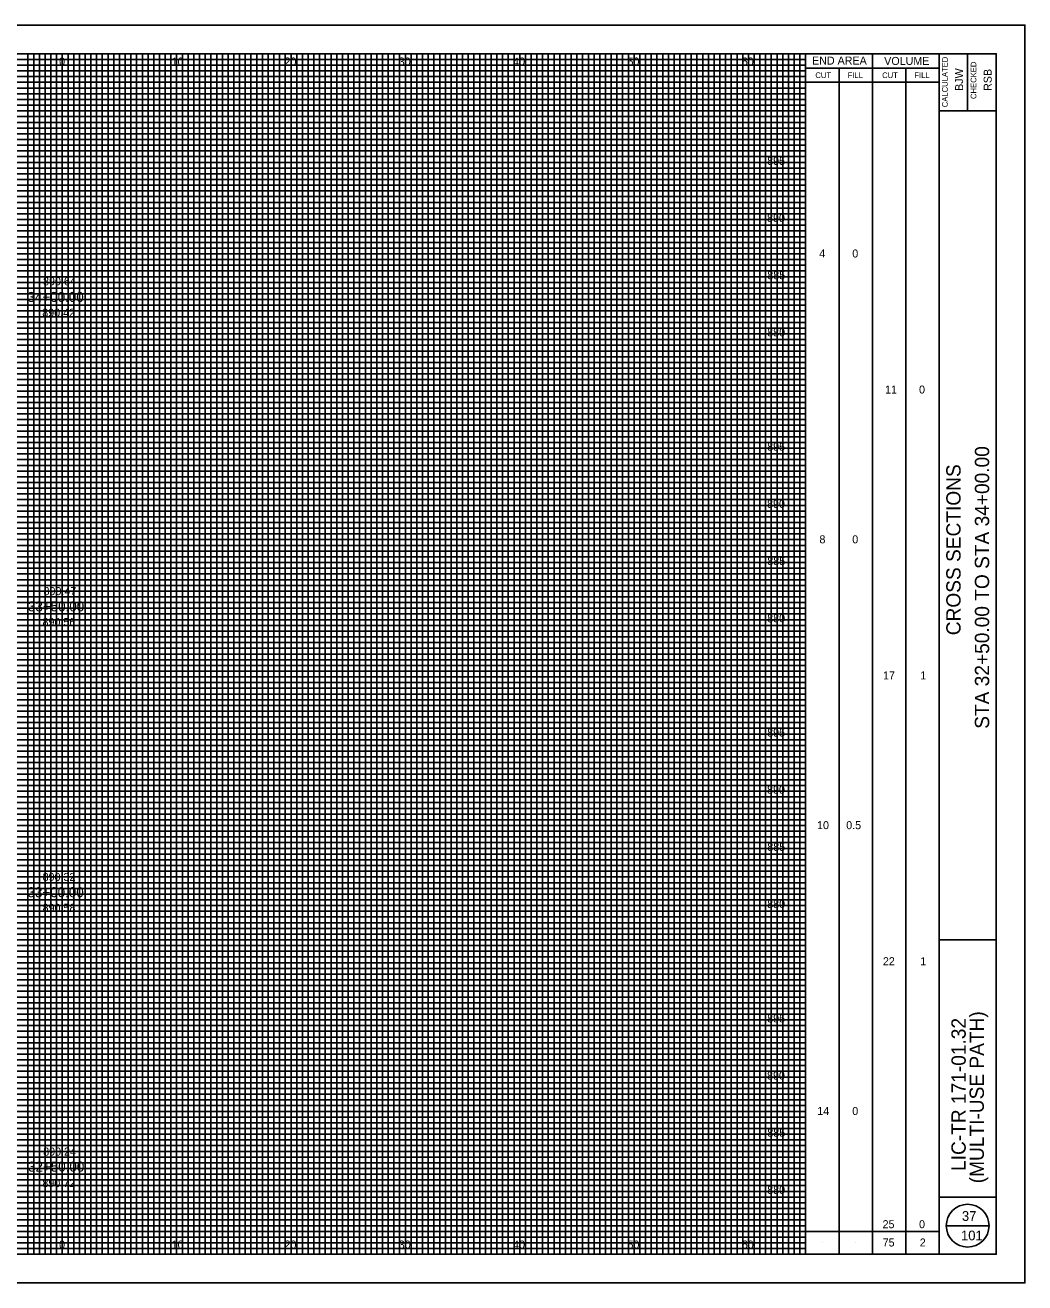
# Model space of a CAD drawing. Extents: x -10 to 160, y -2 to 2522.
# Drawn here: x 72.6 to 160, y 1032.5 to 1142.5 of the extents above; entities that cross this region are included whole.
import ezdxf

# ---------------------------------------------------------------- set-up
doc = ezdxf.new("R2010")
doc.units = 0
for name, color, linetype in [('GK_Cells', 7, 'Continuous'), ('GK_Patterns', 7, 'Continuous'), ('TX_P_10', 7, 'Continuous'), ('TX_X_10', 7, 'Continuous'), ('XS_P_Finished_Grade_Seeded', 7, 'Continuous'), ('XS_P_Pavt_Surface', 7, 'Continuous'), ('XS_P_Subgrade', 7, 'Continuous'), ('XS_X_Ground_Line', 7, 'Continuous')]:
    doc.layers.add(name, color=color, linetype=linetype)

msp = doc.modelspace()

# ---------------------------------------------------------------- linework, layer by layer
at = {"layer": 'GK_Cells'}
msp.add_lwpolyline([(-10, 1032.5), (160, 1032.5), (160, 1142.5), (-10, 1142.5)], close=True, dxfattribs=at)
at = {"layer": 'TX_P_10'}
for p, q in [((140.83, 1035), (140.83, 1140)), ((146.67, 1035), (146.67, 1140)), ((140.83, 1138.75), (152.5, 1138.75)), ((143.75, 1035), (143.75, 1138.75)), ((149.58, 1035), (149.58, 1138.75)), ((140.83, 1137.5), (152.5, 1137.5)), ((153.12, 1037.5), (156.88, 1037.5)), ((140.83, 1037), (152.5, 1037)), ((142.29, 1036), (142.29, 1036)), ((145.21, 1036), (145.21, 1036)), ((148.12, 1036), (148.12, 1036)), ((151.04, 1036), (151.04, 1036))]:
    msp.add_line(p, q, dxfattribs=at)
msp.add_circle((155, 1037.5), 1.87, dxfattribs=at)
at = {"layer": 'TX_X_10'}
for p, q in [((75.83, 1035), (75.83, 1140)), ((80.83, 1035), (80.83, 1140)), ((85.83, 1035), (85.83, 1140)), ((90.83, 1035), (90.83, 1140)), ((95.83, 1035), (95.83, 1140)), ((100.83, 1035), (100.83, 1140)), ((105.83, 1035), (105.83, 1140)), ((110.83, 1035), (110.83, 1140)), ((115.83, 1035), (115.83, 1140)), ((120.83, 1035), (120.83, 1140)), ((125.83, 1035), (125.83, 1140)), ((130.83, 1035), (130.83, 1140)), ((135.83, 1035), (135.83, 1140)), ((5.83, 1135), (140.83, 1135)), ((5.83, 1130), (140.83, 1130)), ((5.83, 1125), (140.83, 1125)), ((5.83, 1120), (140.83, 1120)), ((5.83, 1115), (140.83, 1115)), ((5.83, 1110), (140.83, 1110)), ((5.83, 1105), (140.83, 1105)), ((5.83, 1100), (140.83, 1100)), ((5.83, 1095), (140.83, 1095)), ((5.83, 1090), (140.83, 1090)), ((5.83, 1085), (140.83, 1085)), ((5.83, 1080), (140.83, 1080)), ((5.83, 1075), (140.83, 1075)), ((5.83, 1070), (140.83, 1070)), ((5.83, 1065), (140.83, 1065)), ((5.83, 1060), (140.83, 1060)), ((5.83, 1055), (140.83, 1055)), ((5.83, 1050), (140.83, 1050)), ((5.83, 1045), (140.83, 1045)), ((5.83, 1040), (140.83, 1040))]:
    msp.add_line(p, q, dxfattribs=at)
at = {"layer": 'XS_P_Pavt_Surface'}
for p, q in [((152.5, 1035), (152.5, 1140)), ((155, 1140), (155, 1135)), ((152.5, 1135), (157.5, 1135)), ((152.5, 1062.5), (157.5, 1062.5)), ((152.5, 1040), (157.5, 1040))]:
    msp.add_line(p, q, dxfattribs=at)
msp.add_lwpolyline([(0, 1140), (157.5, 1140), (157.5, 1035), (0, 1035)], close=True, dxfattribs=at)
at = {"layer": 'XS_X_Ground_Line'}
for p, q in [((72.83, 1035), (72.83, 1140)), ((73.33, 1035), (73.33, 1140)), ((73.83, 1035), (73.83, 1140)), ((74.33, 1035), (74.33, 1140)), ((74.83, 1035), (74.83, 1140)), ((75.33, 1035), (75.33, 1140)), ((76.33, 1035), (76.33, 1140)), ((76.83, 1035), (76.83, 1140)), ((77.33, 1035), (77.33, 1140)), ((77.83, 1035), (77.83, 1140)), ((78.33, 1035), (78.33, 1140)), ((78.83, 1035), (78.83, 1140)), ((79.33, 1035), (79.33, 1140)), ((79.83, 1035), (79.83, 1140)), ((80.33, 1035), (80.33, 1140)), ((81.33, 1035), (81.33, 1140)), ((81.83, 1035), (81.83, 1140)), ((82.33, 1035), (82.33, 1140)), ((82.83, 1035), (82.83, 1140)), ((83.33, 1035), (83.33, 1140)), ((83.83, 1035), (83.83, 1140)), ((84.33, 1035), (84.33, 1140)), ((84.83, 1035), (84.83, 1140)), ((85.33, 1035), (85.33, 1140)), ((86.33, 1035), (86.33, 1140)), ((86.83, 1035), (86.83, 1140)), ((87.33, 1035), (87.33, 1140)), ((87.83, 1035), (87.83, 1140)), ((88.33, 1035), (88.33, 1140)), ((88.83, 1035), (88.83, 1140)), ((89.33, 1035), (89.33, 1140)), ((89.83, 1035), (89.83, 1140)), ((90.33, 1035), (90.33, 1140)), ((91.33, 1035), (91.33, 1140)), ((91.83, 1035), (91.83, 1140)), ((92.33, 1035), (92.33, 1140)), ((92.83, 1035), (92.83, 1140)), ((93.33, 1035), (93.33, 1140)), ((93.83, 1035), (93.83, 1140)), ((94.33, 1035), (94.33, 1140)), ((94.83, 1035), (94.83, 1140)), ((95.33, 1035), (95.33, 1140)), ((96.33, 1035), (96.33, 1140)), ((96.83, 1035), (96.83, 1140)), ((97.33, 1035), (97.33, 1140)), ((97.83, 1035), (97.83, 1140)), ((98.33, 1035), (98.33, 1140)), ((98.83, 1035), (98.83, 1140)), ((99.33, 1035), (99.33, 1140)), ((99.83, 1035), (99.83, 1140)), ((100.33, 1035), (100.33, 1140)), ((101.33, 1035), (101.33, 1140)), ((101.83, 1035), (101.83, 1140)), ((102.33, 1035), (102.33, 1140)), ((102.83, 1035), (102.83, 1140)), ((103.33, 1035), (103.33, 1140)), ((103.83, 1035), (103.83, 1140)), ((104.33, 1035), (104.33, 1140)), ((104.83, 1035), (104.83, 1140)), ((105.33, 1035), (105.33, 1140)), ((106.33, 1035), (106.33, 1140)), ((106.83, 1035), (106.83, 1140)), ((107.33, 1035), (107.33, 1140)), ((107.83, 1035), (107.83, 1140)), ((108.33, 1035), (108.33, 1140)), ((108.83, 1035), (108.83, 1140)), ((109.33, 1035), (109.33, 1140)), ((109.83, 1035), (109.83, 1140)), ((110.33, 1035), (110.33, 1140)), ((111.33, 1035), (111.33, 1140)), ((111.83, 1035), (111.83, 1140)), ((112.33, 1035), (112.33, 1140)), ((112.83, 1035), (112.83, 1140)), ((113.33, 1035), (113.33, 1140)), ((113.83, 1035), (113.83, 1140)), ((114.33, 1035), (114.33, 1140)), ((114.83, 1035), (114.83, 1140)), ((115.33, 1035), (115.33, 1140)), ((116.33, 1035), (116.33, 1140)), ((116.83, 1035), (116.83, 1140)), ((117.33, 1035), (117.33, 1140)), ((117.83, 1035), (117.83, 1140)), ((118.33, 1035), (118.33, 1140)), ((118.83, 1035), (118.83, 1140)), ((119.33, 1035), (119.33, 1140)), ((119.83, 1035), (119.83, 1140)), ((120.33, 1035), (120.33, 1140)), ((121.33, 1035), (121.33, 1140)), ((121.83, 1035), (121.83, 1140)), ((122.33, 1035), (122.33, 1140)), ((122.83, 1035), (122.83, 1140)), ((123.33, 1035), (123.33, 1140)), ((123.83, 1035), (123.83, 1140)), ((124.33, 1035), (124.33, 1140)), ((124.83, 1035), (124.83, 1140)), ((125.33, 1035), (125.33, 1140)), ((126.33, 1035), (126.33, 1140)), ((126.83, 1035), (126.83, 1140)), ((127.33, 1035), (127.33, 1140)), ((127.83, 1035), (127.83, 1140)), ((128.33, 1035), (128.33, 1140)), ((128.83, 1035), (128.83, 1140)), ((129.33, 1035), (129.33, 1140)), ((129.83, 1035), (129.83, 1140)), ((130.33, 1035), (130.33, 1140)), ((131.33, 1035), (131.33, 1140)), ((131.83, 1035), (131.83, 1140)), ((132.33, 1035), (132.33, 1140)), ((132.83, 1035), (132.83, 1140)), ((133.33, 1035), (133.33, 1140)), ((133.83, 1035), (133.83, 1140)), ((134.33, 1035), (134.33, 1140)), ((134.83, 1035), (134.83, 1140)), ((135.33, 1035), (135.33, 1140)), ((136.33, 1035), (136.33, 1140)), ((136.83, 1035), (136.83, 1140)), ((137.33, 1035), (137.33, 1140)), ((137.83, 1035), (137.83, 1140)), ((138.33, 1035), (138.33, 1140)), ((138.83, 1035), (138.83, 1140)), ((139.33, 1035), (139.33, 1140)), ((139.83, 1035), (139.83, 1140)), ((140.33, 1035), (140.33, 1140)), ((5.83, 1139.5), (140.83, 1139.5)), ((5.83, 1139), (140.83, 1139)), ((5.83, 1138.5), (140.83, 1138.5)), ((5.83, 1138), (140.83, 1138)), ((5.83, 1137.5), (140.83, 1137.5)), ((5.83, 1137), (140.83, 1137)), ((5.83, 1136.5), (140.83, 1136.5)), ((5.83, 1136), (140.83, 1136)), ((5.83, 1135.5), (140.83, 1135.5)), ((5.83, 1134.5), (140.83, 1134.5)), ((5.83, 1134), (140.83, 1134)), ((5.83, 1133.5), (140.83, 1133.5)), ((5.83, 1133), (140.83, 1133)), ((5.83, 1132.5), (140.83, 1132.5)), ((5.83, 1132), (140.83, 1132)), ((5.83, 1131.5), (140.83, 1131.5)), ((5.83, 1131), (140.83, 1131)), ((5.83, 1130.5), (140.83, 1130.5)), ((5.83, 1129.5), (140.83, 1129.5)), ((5.83, 1129), (140.83, 1129)), ((5.83, 1128.5), (140.83, 1128.5)), ((5.83, 1128), (140.83, 1128)), ((5.83, 1127.5), (140.83, 1127.5)), ((5.83, 1127), (140.83, 1127)), ((5.83, 1126.5), (140.83, 1126.5)), ((5.83, 1126), (140.83, 1126)), ((5.83, 1125.5), (140.83, 1125.5)), ((5.83, 1124.5), (140.83, 1124.5)), ((5.83, 1124), (140.83, 1124)), ((5.83, 1123.5), (140.83, 1123.5)), ((5.83, 1123), (140.83, 1123)), ((5.83, 1122.5), (140.83, 1122.5)), ((5.83, 1122), (140.83, 1122)), ((5.83, 1121.5), (140.83, 1121.5)), ((5.83, 1121), (140.83, 1121)), ((5.83, 1120.5), (140.83, 1120.5)), ((5.83, 1119.5), (140.83, 1119.5)), ((5.83, 1119), (140.83, 1119)), ((5.83, 1118.5), (140.83, 1118.5)), ((5.83, 1118), (140.83, 1118)), ((5.83, 1117.5), (140.83, 1117.5)), ((5.83, 1117), (140.83, 1117)), ((5.83, 1116.5), (140.83, 1116.5)), ((5.83, 1116), (140.83, 1116)), ((5.83, 1115.5), (140.83, 1115.5)), ((5.83, 1114.5), (140.83, 1114.5)), ((5.83, 1114), (140.83, 1114)), ((5.83, 1113.5), (140.83, 1113.5)), ((5.83, 1113), (140.83, 1113)), ((5.83, 1112.5), (140.83, 1112.5)), ((5.83, 1112), (140.83, 1112)), ((5.83, 1111.5), (140.83, 1111.5)), ((5.83, 1111), (140.83, 1111)), ((5.83, 1110.5), (140.83, 1110.5)), ((5.83, 1109.5), (140.83, 1109.5)), ((5.83, 1109), (140.83, 1109)), ((5.83, 1108.5), (140.83, 1108.5)), ((5.83, 1108), (140.83, 1108)), ((5.83, 1107.5), (140.83, 1107.5)), ((5.83, 1107), (140.83, 1107)), ((5.83, 1106.5), (140.83, 1106.5)), ((5.83, 1106), (140.83, 1106)), ((5.83, 1105.5), (140.83, 1105.5)), ((5.83, 1104.5), (140.83, 1104.5)), ((5.83, 1104), (140.83, 1104)), ((5.83, 1103.5), (140.83, 1103.5)), ((5.83, 1103), (140.83, 1103)), ((5.83, 1102.5), (140.83, 1102.5)), ((5.83, 1102), (140.83, 1102)), ((5.83, 1101.5), (140.83, 1101.5)), ((5.83, 1101), (140.83, 1101)), ((5.83, 1100.5), (140.83, 1100.5)), ((5.83, 1099.5), (140.83, 1099.5)), ((5.83, 1099), (140.83, 1099)), ((5.83, 1098.5), (140.83, 1098.5)), ((5.83, 1098), (140.83, 1098)), ((5.83, 1097.5), (140.83, 1097.5)), ((5.83, 1097), (140.83, 1097)), ((5.83, 1096.5), (140.83, 1096.5)), ((5.83, 1096), (140.83, 1096)), ((5.83, 1095.5), (140.83, 1095.5)), ((5.83, 1094.5), (140.83, 1094.5)), ((5.83, 1094), (140.83, 1094)), ((5.83, 1093.5), (140.83, 1093.5)), ((5.83, 1093), (140.83, 1093)), ((5.83, 1092.5), (140.83, 1092.5)), ((5.83, 1092), (140.83, 1092)), ((5.83, 1091.5), (140.83, 1091.5)), ((5.83, 1091), (140.83, 1091)), ((5.83, 1090.5), (140.83, 1090.5)), ((5.83, 1089.5), (140.83, 1089.5)), ((5.83, 1089), (140.83, 1089)), ((5.83, 1088.5), (140.83, 1088.5)), ((5.83, 1088), (140.83, 1088)), ((5.83, 1087.5), (140.83, 1087.5)), ((5.83, 1087), (140.83, 1087)), ((5.83, 1086.5), (140.83, 1086.5)), ((5.83, 1086), (140.83, 1086)), ((5.83, 1085.5), (140.83, 1085.5)), ((5.83, 1084.5), (140.83, 1084.5)), ((5.83, 1084), (140.83, 1084)), ((5.83, 1083.5), (140.83, 1083.5)), ((5.83, 1083), (140.83, 1083)), ((5.83, 1082.5), (140.83, 1082.5)), ((5.83, 1082), (140.83, 1082)), ((5.83, 1081.5), (140.83, 1081.5)), ((5.83, 1081), (140.83, 1081)), ((5.83, 1080.5), (140.83, 1080.5)), ((5.83, 1079.5), (140.83, 1079.5)), ((5.83, 1079), (140.83, 1079)), ((5.83, 1078.5), (140.83, 1078.5)), ((5.83, 1078), (140.83, 1078)), ((5.83, 1077.5), (140.83, 1077.5)), ((5.83, 1077), (140.83, 1077)), ((5.83, 1076.5), (140.83, 1076.5)), ((5.83, 1076), (140.83, 1076)), ((5.83, 1075.5), (140.83, 1075.5)), ((5.83, 1074.5), (140.83, 1074.5)), ((5.83, 1074), (140.83, 1074)), ((5.83, 1073.5), (140.83, 1073.5)), ((5.83, 1073), (140.83, 1073)), ((5.83, 1072.5), (140.83, 1072.5)), ((5.83, 1072), (140.83, 1072)), ((5.83, 1071.5), (140.83, 1071.5)), ((5.83, 1071), (140.83, 1071)), ((5.83, 1070.5), (140.83, 1070.5)), ((5.83, 1069.5), (140.83, 1069.5)), ((5.83, 1069), (140.83, 1069)), ((5.83, 1068.5), (140.83, 1068.5)), ((5.83, 1068), (140.83, 1068)), ((5.83, 1067.5), (140.83, 1067.5)), ((5.83, 1067), (140.83, 1067)), ((5.83, 1066.5), (140.83, 1066.5)), ((5.83, 1066), (140.83, 1066)), ((5.83, 1065.5), (140.83, 1065.5)), ((5.83, 1064.5), (140.83, 1064.5)), ((5.83, 1064), (140.83, 1064)), ((5.83, 1063.5), (140.83, 1063.5)), ((5.83, 1063), (140.83, 1063)), ((5.83, 1062.5), (140.83, 1062.5)), ((5.83, 1062), (140.83, 1062)), ((5.83, 1061.5), (140.83, 1061.5)), ((5.83, 1061), (140.83, 1061)), ((5.83, 1060.5), (140.83, 1060.5)), ((5.83, 1059.5), (140.83, 1059.5)), ((5.83, 1059), (140.83, 1059)), ((5.83, 1058.5), (140.83, 1058.5)), ((5.83, 1058), (140.83, 1058)), ((5.83, 1057.5), (140.83, 1057.5)), ((5.83, 1057), (140.83, 1057)), ((5.83, 1056.5), (140.83, 1056.5)), ((5.83, 1056), (140.83, 1056)), ((5.83, 1055.5), (140.83, 1055.5)), ((5.83, 1054.5), (140.83, 1054.5)), ((5.83, 1054), (140.83, 1054)), ((5.83, 1053.5), (140.83, 1053.5)), ((5.83, 1053), (140.83, 1053)), ((5.83, 1052.5), (140.83, 1052.5)), ((5.83, 1052), (140.83, 1052)), ((5.83, 1051.5), (140.83, 1051.5)), ((5.83, 1051), (140.83, 1051)), ((5.83, 1050.5), (140.83, 1050.5)), ((5.83, 1049.5), (140.83, 1049.5)), ((5.83, 1049), (140.83, 1049)), ((5.83, 1048.5), (140.83, 1048.5)), ((5.83, 1048), (140.83, 1048)), ((5.83, 1047.5), (140.83, 1047.5)), ((5.83, 1047), (140.83, 1047)), ((5.83, 1046.5), (140.83, 1046.5)), ((5.83, 1046), (140.83, 1046)), ((5.83, 1045.5), (140.83, 1045.5)), ((5.83, 1044.5), (140.83, 1044.5)), ((5.83, 1044), (140.83, 1044)), ((5.83, 1043.5), (140.83, 1043.5)), ((5.83, 1043), (140.83, 1043)), ((5.83, 1042.5), (140.83, 1042.5)), ((5.83, 1042), (140.83, 1042)), ((5.83, 1041.5), (140.83, 1041.5)), ((5.83, 1041), (140.83, 1041)), ((5.83, 1040.5), (140.83, 1040.5)), ((5.83, 1039.5), (140.83, 1039.5)), ((5.83, 1039), (140.83, 1039)), ((5.83, 1038.5), (140.83, 1038.5)), ((5.83, 1038), (140.83, 1038)), ((5.83, 1037.5), (140.83, 1037.5)), ((5.83, 1037), (140.83, 1037)), ((5.83, 1036.5), (140.83, 1036.5)), ((5.83, 1036), (140.83, 1036)), ((5.83, 1035.5), (140.83, 1035.5))]:
    msp.add_line(p, q, dxfattribs=at)

# ---------------------------------------------------------------- texts
at = {"layer": 'GK_Patterns'}
for s, height, p in [('0', 0.7, (75.55, 1138.97)), ('0', 0.7, (75.55, 1138.97)), ('10', 0.7, (85.39, 1138.97)), ('20', 0.7, (95.26, 1138.97)), ('30', 0.7, (105.25, 1138.97)), ('40', 0.7, (115.25, 1138.97)), ('50', 0.7, (125.25, 1138.97)), ('60', 0.7, (135.25, 1138.97)), ('895', 0.7, (137.47, 1130.28)), ('890', 0.7, (137.46, 1125.28)), ('4', 0.7, (142.02, 1122.18)), ('0', 0.7, (144.91, 1122.18)), ('885', 0.7, (137.48, 1120.28)), ('34+00.00', 0.875, (72.79, 1118.29)), ('880', 0.7, (137.47, 1115.28)), ('11', 0.7, (147.78, 1110.28)), ('0', 0.7, (150.75, 1110.28)), ('895', 0.7, (137.47, 1105.28)), ('890', 0.7, (137.46, 1100.28)), ('8', 0.7, (142.04, 1097.18)), ('0', 0.7, (144.91, 1097.18)), ('885', 0.7, (137.48, 1095.28)), ('33+50.00', 0.875, (72.83, 1091.23)), ('880', 0.7, (137.47, 1090.28)), ('17', 0.7, (147.6, 1085.28)), ('1', 0.7, (150.86, 1085.28)), ('895', 0.7, (137.47, 1080.28)), ('890', 0.7, (137.46, 1075.28)), ('10', 0.7, (141.83, 1072.18)), ('0.5', 0.7, (144.38, 1072.18)), ('885', 0.7, (137.48, 1070.28)), ('33+00.00', 0.875, (72.79, 1066.23)), ('880', 0.7, (137.47, 1065.28)), ('22', 0.7, (147.59, 1060.28)), ('1', 0.7, (150.86, 1060.28)), ('895', 0.7, (137.47, 1055.28)), ('890', 0.7, (137.46, 1050.28)), ('14', 0.7, (141.85, 1047.18)), ('0', 0.7, (144.91, 1047.18)), ('885', 0.7, (137.48, 1045.28)), ('32+50.00', 0.875, (72.84, 1042.23)), ('880', 0.7, (137.47, 1040.28)), ('25', 0.7, (147.56, 1037.28)), ('0', 0.7, (150.75, 1037.28)), ('0', 0.7, (75.55, 1035.5)), ('0', 0.7, (75.55, 1035.5)), ('10', 0.7, (85.39, 1035.5)), ('20', 0.7, (95.26, 1035.5)), ('30', 0.7, (105.25, 1035.5)), ('40', 0.7, (115.25, 1035.5)), ('50', 0.7, (125.25, 1035.5)), ('60', 0.7, (135.25, 1035.5)), ('75', 0.7, (147.57, 1035.68)), ('2', 0.7, (150.81, 1035.68))]:
    msp.add_text(s, height=height, dxfattribs=at).set_placement(p)
at = {"layer": 'TX_P_10'}
for s, height, p in [('END AREA', 0.7, (141.39, 1139.05)), ('VOLUME', 0.7, (147.7, 1139.02)), ('CUT', 0.5, (141.68, 1137.87)), ('FILL', 0.5, (144.5, 1137.87)), ('CUT', 0.5, (147.52, 1137.87)), ('FILL', 0.5, (150.34, 1137.87)), ('37', 0.85, (154.5, 1037.92)), ('101', 0.85, (154.42, 1036.22))]:
    msp.add_text(s, height=height, dxfattribs=at).set_placement(p)
for s, height, p in [('CALCULATED', 0.5, (153.26, 1135.32)), ('BJW', 0.7, (154.6, 1136.75)), ('CHECKED', 0.5, (155.76, 1136.04)), ('RSB', 0.7, (157.1, 1136.75)), ('STA 32+50.00 TO STA 34+00.00', 1.25, (156.88, 1080.96)), ('CROSS SECTIONS', 1.25, (154.38, 1089.14)), ('(MULTI-USE PATH)', 1.25, (156.42, 1041.21)), ('LIC-TR 171-01.32', 1.25, (154.83, 1042.29))]:
    msp.add_text(s, height=height, rotation=90, dxfattribs=at).set_placement(p)
at = {"layer": 'XS_P_Finished_Grade_Seeded'}
for s, p in [('890.42', (74.08, 1117)), ('890.56', (74.1, 1089.95)), ('890.58', (74.11, 1064.95)), ('890.72', (74.09, 1040.87))]:
    msp.add_text(s, height=0.7, dxfattribs=at).set_placement(p)
at = {"layer": 'XS_P_Subgrade'}
for s, p in [('890.64', (74.15, 1119.75)), ('890.47', (74.19, 1092.65)), ('890.32', (74.11, 1067.65)), ('890.24', (74.16, 1043.63))]:
    msp.add_text(s, height=0.7, dxfattribs=at).set_placement(p)

doc.saveas('drawing.dxf')
